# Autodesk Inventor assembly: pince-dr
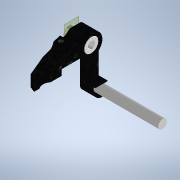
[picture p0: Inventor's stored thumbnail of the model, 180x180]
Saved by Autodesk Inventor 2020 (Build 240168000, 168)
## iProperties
Created: 2023-10
Part Number: pince-dr
Document SubType Name: Assembly
Designer: bruno
Author: bruno
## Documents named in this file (5)
- C:\Users\bruno\Documents\1-Cours-2023-24\Maquettes-Inventor\Pince-robot-Dobot\HS422\pince-dr.iam
- C:\Users\bruno\Documents\1-Cours-2023-24\Maquettes-Inventor\Pince-robot-Dobot\pince-d.ipt
- C:\Users\bruno\Documents\1-Cours-2023-24\Maquettes-Inventor\Pince-robot-Dobot\Tige-verin.ipt
- C:\Users\bruno\Documents\1-Cours-2023-24\Maquettes-Inventor\Pince-robot-Dobot\Douille.ipt
- C:\Users\bruno\Documents\Inventor\Content Center Files\R2020\fr-FR\KS B 1003\KS B 1003 - M 2 x 5.ipt
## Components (4 placed, 4 different names)
1. pince-d:1 — Placage:1, Affleurement:1, Placage:2, Placage:3, Placage:4, Logement:1
2. Tige-verin:1 — Placage:1, Placage:3, Placage:4
3. Douille:1 — Affleurement:1, Placage:2
4. KS B 1003 - Métrique M 2 x 5:1 — Logement:1
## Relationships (6: Mate 4, Flush 1, Insert 1)
- Placage:1 [Mate]: pince-d:1 ↔ Tige-verin:1
- Affleurement:1 [Flush]: pince-d:1 ↔ Douille:1
- Placage:2 [Mate]: pince-d:1 ↔ Douille:1
- Placage:3 [Mate]: pince-d:1 ↔ Tige-verin:1
- Placage:4 [Mate]: pince-d:1 ↔ Tige-verin:1
- Logement:1 [Insert]: pince-d:1 ↔ KS B 1003 - Métrique M 2 x 5:1
